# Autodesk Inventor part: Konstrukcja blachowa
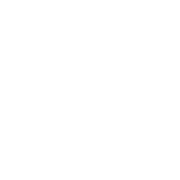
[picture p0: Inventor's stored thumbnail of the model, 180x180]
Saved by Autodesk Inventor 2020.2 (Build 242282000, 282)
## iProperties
Part Number: Konstrukcja blachowa
Material: Stal
Document SubType Name: Konstrukcja blachowa
Density: 7.85 g/cm^3
Sheet Metal Rule: Blacha stalowa 1.0 mm/Spoina liniowa
Appearance: Stal
Created: 2016-06
Designer: F.Stasiak
Manager: www.cadconsulting.pl
Company: Fabian Stasiak CAD Consulting
FLATAREA: =<FLAT PATTERN AREA>
Grubość: 1
Subject: Zbiór ćwiczeń. Autodesk Inventor 2020. Kurs podstawowy
Author: F.Stasiak
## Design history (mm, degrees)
other parameters: "Grubość" = 1 (derived), "WspółczynnikK" = 4.4, "PromieńGięcia" = 1 (= Grubość), "SzerokośćGięciaPodcięcia" = 1 (= Grubość), "GłębokośćGięciaPodcięcia" = 0.5 (= 0.5 x Grubość), "RozmiarPodcięciaNarożnika" = 4 (= 4 x Grubość), "OdstępPołączenia" = 0.01, "MinimalnaPozostałość" = 2 (= 2 x Grubość), "PromieńPrzejścia" = 1 (= PromieńGięcia), "Rozmiar_promienia_Jacobiego" = 1 (= PromieńGięcia), "Wielk_odstępu" = 1 (= Grubość)
